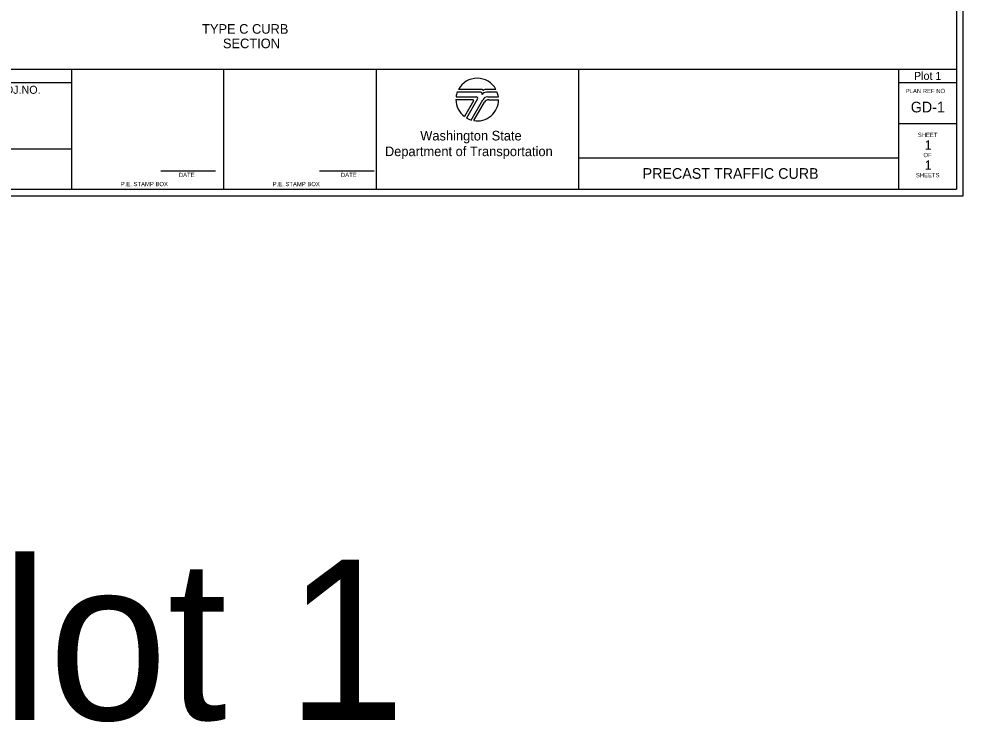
# Model space of a CAD drawing. Extents: x 99988 to 100172, y 99995 to 100047.
# Drawn here: x 100006.96 to 100015.81, y 99995.01 to 100001.6 of the extents above; entities that cross this region are included whole.
import ezdxf

# ---------------------------------------------------------------- set-up
doc = ezdxf.new("R2010")
doc.units = 0
for name, color, linetype in [('Level 20', 7, 'Continuous'), ('SH_GI_PlotLimits', 7, 'Continuous'), ('SH_GI_SheetBorder', 7, 'Continuous'), ('SH_GI_SheetLocationText', 7, 'Continuous'), ('SH_GI_SheetTextInCells', 7, 'Continuous'), ('SH_GI_TitleBlockText', 7, 'Continuous'), ('SH_GI_WSDOTLogo', 7, 'Continuous')]:
    doc.layers.add(name, color=color, linetype=linetype)

msp = doc.modelspace()

# ---------------------------------------------------------------- linework, layer by layer
at = {"layer": 'SH_GI_PlotLimits'}
msp.add_lwpolyline([(99999.3125, 99999.9375), (100015.8125, 99999.9375), (100015.8125, 100010.4375), (99999.3125, 100010.4375)], close=True, dxfattribs=at)
at = {"layer": 'SH_GI_SheetBorder'}
for p, q in [((100015.75, 100010.375), (100015.75, 100000)), ((100000, 100001.1259), (100015.75, 100001.1259)), ((100007.4566, 100000), (100007.4566, 100001.1259)), ((100008.8828, 100000), (100008.8828, 100001.1259)), ((100010.3089, 100001.1259), (100010.3089, 100000)), ((100012.2055, 100001.1259), (100012.2055, 100000)), ((100015.2079, 100001.1259), (100015.2079, 100000)), ((100000, 100001.0008), (100007.4566, 100001.0008)), ((100015.2079, 100001.0008), (100015.75, 100001.0008)), ((100015.2079, 100000.6176), (100015.75, 100000.6176)), ((100007.4566, 100000.3753), (100005.4466, 100000.3753)), ((100012.2055, 100000.2955), (100015.2079, 100000.2955)), ((100008.2903, 100000.1733), (100008.802, 100000.1733)), ((100009.7797, 100000.1733), (100010.2914, 100000.1733)), ((100000, 100000), (100015.75, 100000))]:
    msp.add_line(p, q, dxfattribs=at)
at = {"layer": 'SH_GI_WSDOTLogo'}
for p, q in [((100011.059, 100000.8661), (100011.2496, 100000.8661)), ((100011.2894, 100000.9094), (100011.0697, 100000.9094)), ((100011.303, 100000.9354), (100011.0815, 100000.9354)), ((100011.433, 100000.9354), (100011.3351, 100000.9354)), ((100011.343, 100000.9094), (100011.3429, 100000.9094)), ((100011.4448, 100000.9094), (100011.343, 100000.9094)), ((100011.3558, 100000.8661), (100011.4555, 100000.8661)), ((100011.0572, 100000.84), (100011.2148, 100000.84)), ((100011.222, 100000.8277), (100011.1364, 100000.6807)), ((100011.261, 100000.8464), (100011.1567, 100000.6672)), ((100011.1989, 100000.6487), (100011.3089, 100000.839)), ((100011.2244, 100000.6428), (100011.3242, 100000.8156)), ((100011.3655, 100000.8394), (100011.4572, 100000.8394))]:
    msp.add_line(p, q, dxfattribs=at)
for centre, radius, start, end in [((100011.2572, 100000.84), 0.2, 28.47865, 151.53204), ((100011.2572, 100000.84), 0.2, 159.69598, 172.50569), ((100011.2497, 100000.853), 0.0131, 329.76834, 90), ((100011.2894, 100000.8946), 0.0148, 327.8418, 89.99855), ((100011.3429, 100000.861), 0.0484, 89.99529, 147.82376), ((100011.303, 100000.9263), 0.00903, 329.87418, 90.00328), ((100011.3558, 100000.8119), 0.0542, 90, 149.99738), ((100011.3352, 100000.9066), 0.0287, 90.00721, 148.16763), ((100011.2572, 100000.84), 0.2, 7.49431, 20.29406), ((100011.2572, 100000.84), 0.2, 179.99864, 232.84327), ((100011.2149, 100000.8318), 0.0082, 329.74356, 90), ((100011.2572, 100000.84), 0.2, 260.54554, 359.80857), ((100011.3654, 100000.7918), 0.0476, 90, 150.05432), ((100011.2572, 100000.84), 0.2, 239.79292, 253.0448)]:
    msp.add_arc(centre, radius, start, end, dxfattribs=at)

# ---------------------------------------------------------------- texts
at = {"layer": 'Level 20'}
for s, p in [('TYPE C CURB', (100008.6775, 100001.4575)), ('SECTION', (100008.8727, 100001.3218))]:
    msp.add_text(s, height=0.09, dxfattribs=at).set_placement(p)
at = {"layer": 'SH_GI_SheetBorder'}
msp.add_text('PLAN REF NO', height=0.040032, dxfattribs=at).set_placement((100015.2747, 100000.9008))
at = {"layer": 'SH_GI_SheetLocationText'}
for height, p in [(0.075, (100015.3518, 100001.025)), (1.5, (100005.4547, 99995.0267))]:
    msp.add_text('Plot 1', height=height, dxfattribs=at).set_placement(p)
at = {"layer": 'SH_GI_SheetTextInCells'}
for s, height, p in [('FED.AID PROJ.NO.', 0.07506, (100006.2652, 100000.8945)), ('Washington State', 0.090072, (100010.7229, 100000.4571)), ('SHEET', 0.04003, (100015.3877, 100000.4896)), ('Department of Transportation', 0.090072, (100010.3916, 100000.3101)), ('OF', 0.04003, (100015.4406, 100000.3008)), ('DATE', 0.04003, (100008.4597, 100000.1141)), ('DATE', 0.04003, (100009.9794, 100000.1141)), ('SHEETS', 0.04003, (100015.3698, 100000.112)), ('P.E. STAMP BOX', 0.040032, (100007.915, 100000.0286)), ('P.E. STAMP BOX', 0.040032, (100009.339, 100000.0286))]:
    msp.add_text(s, height=height, dxfattribs=at).set_placement(p)
at = {"layer": 'SH_GI_TitleBlockText'}
for s, height, p in [('GD-1', 0.1, (100015.3219, 100000.72)), ('1', 0.085, (100015.453, 100000.3723)), ('1', 0.085, (100015.453, 100000.1843)), ('PRECAST TRAFFIC CURB', 0.1, (100012.8079, 100000.0977))]:
    msp.add_text(s, height=height, dxfattribs=at).set_placement(p)

doc.saveas('drawing.dxf')
